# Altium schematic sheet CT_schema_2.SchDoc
size 293 x 156 mm
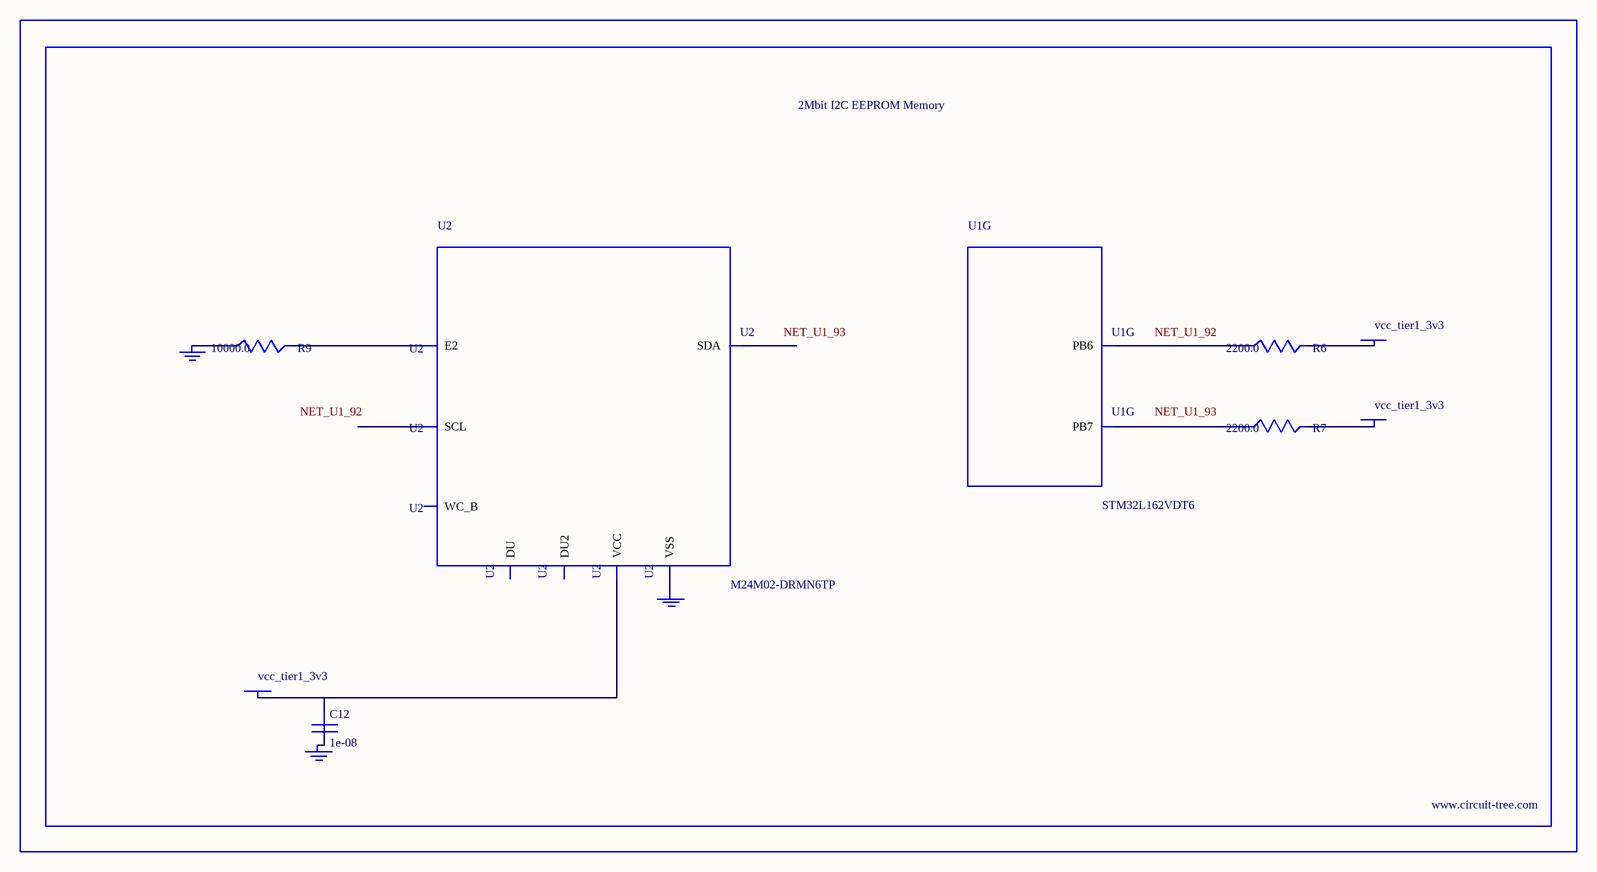
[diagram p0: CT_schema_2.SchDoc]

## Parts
BORDER1  (no value)
C12  1e-08  [C0402]
GND_INSTANCE_1_0  (no value)
GND_INSTANCE_1_1  (no value)
GND_INSTANCE_1_2  (no value)
POWER_INSTANCE_1_0  vcc_tier1_3v3
POWER_INSTANCE_1_1  vcc_tier1_3v3
POWER_INSTANCE_1_2  vcc_tier1_3v3
R6  2200.0  [R0603]
R7  2200.0  [R0603]
R9  10000.0  [R0603]
U1  STM32L162VDT6  [LQFP100]  (part G of 8)
U2  M24M02-DRMN6TP  [SOIC-8]

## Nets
NetC12_1: C12.1 POWER_INSTANCE_1_0.0(PWR) U2.8(VCC)
NetC12_2: C12.2 GND_INSTANCE_1_1.0(GND)
NetGND_INSTANCE_1_0_0: GND_INSTANCE_1_0.0(GND) R9.1
NetGND_INSTANCE_1_2_0: GND_INSTANCE_1_2.0(GND) U2.4(VSS)
NetPOWER_INSTANCE_1_1_0: POWER_INSTANCE_1_1.0(PWR) R6.2
NetPOWER_INSTANCE_1_2_0: POWER_INSTANCE_1_2.0(PWR) R7.2
NetR6_1: R6.1 U1.92(PB6)
NetR7_1: R7.1 U1.93(PB7)
NetR9_2: R9.2 U2.3(E2)

Not connected (* = marked no-connect by the designer): U2 1(DU) 2(DU2) 5(SDA) 6(SCL) 7(WC_B)

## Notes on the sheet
- Labels drawn without touching a wire or pin: NET_U1_92, NET_U1_93

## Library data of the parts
BORDER1 = BORDER_PAGE1
C12 = C0402C103K3RAC
GND_INSTANCE_1_0-GND_INSTANCE_1_2 = GND
POWER_INSTANCE_1_0-POWER_INSTANCE_1_2 = PWR
R6 R7 = RC0603JR-072K2L
R9 = RC0603JR-0710KL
